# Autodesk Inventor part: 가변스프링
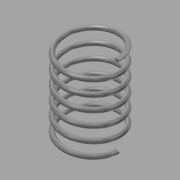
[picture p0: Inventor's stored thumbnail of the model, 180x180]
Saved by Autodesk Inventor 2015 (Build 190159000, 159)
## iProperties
Created: 2016-02
Part Number: 가변스프링
Material: 스테인레스 스틸
Document SubType Name: Modeling
Designer: Administrator
Density: 8 g/cm^3
Appearance: 반연마
Mass: 84.2141 g
Surface Area: 106.444 cm^2
Volume: 10.5268 cm^3
Author: Administrator
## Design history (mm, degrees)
sketch "스케치1"
  geometry: L1 (0, 0)-(-22.5, 0); L2 (-22.5, 0)-(-22.5, 67.25); L3 (-22.5, 67.25)-(0, 67.25); L4 (0, 67.25)-(0, 0); C1 r 2 at (-22.5, 0)
  constraints: 8 end point, 2 parallel, 1 centre point, 1 coincident, 1 horizontal, 1 perpendicular
  dimensions: "d0" = 45 diameter of L2 L4; "d1" = 4 diameter of C1; "d2" = 67.25 distance between parallel lines of L1 L3 (derived)
feature "코일1" sketch "스케치1" pitch "d3" = 10; turns "d5" = 6; dims "d4" = 67.25 (= d2), "d6" = 0, angle "d7" = 90 deg, angle "d8" = 90 deg, "d9" = 0, "d10" = 0
sketch "스케치2"
  geometry: L1 (20.5, 0)-(24.5, 0) reference; 1 further point
  constraints: 1 horizontal alignment
extrude "돌출1" cut sketch "스케치2" stored distance "d11" = 10; taper "d12" = 0 deg
node "작업 평면1"
sketch "스케치3"
  geometry: L1 (-20.5, 0)-(-24.5, 0) reference; 1 further point
  constraints: 1 horizontal alignment
extrude "돌출2" cut sketch "스케치3" stored distance "d13" = 10; taper "d14" = 0 deg
node "솔리드1"
node "절단 모서리 투영1"
node "절단 모서리 투영2"
